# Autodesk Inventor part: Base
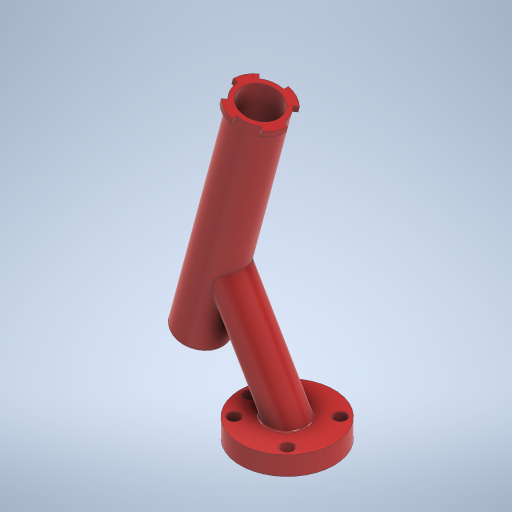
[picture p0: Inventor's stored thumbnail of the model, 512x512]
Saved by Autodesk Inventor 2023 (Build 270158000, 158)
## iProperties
Created: 2026-02
Part Number: Base
Material: Genérico
Document SubType Name: Modeling
Designer: JULIAN
Density: 1 g/cm^3
Appearance: Valor por defecto
Author: JULIAN
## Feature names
1. Extrusión1
2. Barrido1
3. Empalme1 [Fillet]
4. Extrusión2
5. Empalme2 [Fillet]
6. Extrusión3
7. Empalme3 [Fillet]
8. Extrusión4
## Parameters: d2 = 6.3 mm, d3 = 45 deg, d4 = 6.4 mm, d7 = 360 deg, d10 = 0, d15 = 120 deg, d16 = 0, d17 = 0, d18 = 1 mm, d22 = 105 deg, d25 = 25 mm, d26 = 125 mm, d27 = 0, d28 = 2 mm, d32 = 0, d33 = 1 mm, d35 = 25 mm, d36 = 48 deg, d39 = 360 deg, d41 = 3 mm, d42 = 0
